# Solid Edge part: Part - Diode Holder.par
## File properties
Author: hhakima
Template: Normal.par
Last saved by: hhakima
Revision: 8
Application: Solid Edge
Density: 2712.000 kg/m^3
Accuracy: 0.990
Material: Aluminum, 6061-T6
Face Style: Aluminum
Fill Style: ANSI38(Aluminum)
Virtual Style: Polished aluminum
Coef. of Thermal Exp: 2.3e-05
Thermal Conductivity: 180.0
Specific Heat: 920.0
Modulus of Elasticity: 68947570000.0
Poission's Ratio: 0.33
Yield Stress: 275790280.0
Ultimate Stress: 310264065.0
Elongation: 0.0
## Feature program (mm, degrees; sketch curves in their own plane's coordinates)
sketch for "unnamed Protrusion 1" plane through (0, 0, 0) normal (0, 0, 1) x-axis (1, 0, 0)
  circle centre (0, 0) radius 5
extrude "unnamed Protrusion 1" add finite 5.5 along -normal
sketch for "ExtrudedCutout_1" plane through (0, 0, 0) normal (0, 0, 1) x-axis (0, 1, 0)
  circle centre (0, 0) radius 4
extrude "ExtrudedCutout_1" cut finite 2 along -normal
sketch for "ExtrudedCutout_2" plane through (0, 0, -2) normal (0, 0, 1) x-axis (0, 1, 0)
  circle centre (0, 0) radius 2.79
extrude "ExtrudedCutout_2" cut finite 1.2 along -normal
sketch for "unnamed Cutout 1" plane through (0, 0, -3.2) normal (0, 0, 1) x-axis (1, 0, 0)
  circle centre (0, 0) radius 2.25
extrude "unnamed Cutout 1" cut to key point along -normal
sketch for "ExtrudedCutout_4" #1 plane through (0, 0, -5.5) normal (0, 0, -1) x-axis (0, -1, 0)
  circle centre (0, 0) radius 4.35
sketch for "ExtrudedCutout_4" #2 plane through (0, 0, -5.5) normal (0, 0, -1) x-axis (0, -1, 0)
  circle centre (0, 0) radius 5
extrude "ExtrudedCutout_4" cut finite 3 along -normal
sketch for "ExtrudedCutout_5" plane through (0, 0, -5.5) normal (0, 0, -1) x-axis (-1, 0, 0)
  line (-8, -0.5) -> (8, -0.5)
  line (8, -0.5) -> (8, 0.5)
  line (8, 0.5) -> (-8, 0.5)
  line (-8, 0.5) -> (-8, -0.5)
extrude "ExtrudedCutout_5" cut finite 1 along -normal
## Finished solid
Body 1: solid body, 17 faces, 32 edges, 16 vertices.
  Faces by surface: plane 12, cylinder 5
  Edges by curve: circle 16, line 16
Bounding box of the edges (mm): 10.000 x 10.000 x 5.500, from (-5, -5, -5.5) to (5, 5, 0).
Cylindrical faces by radius (mm): R2.25 x1, R2.79 x1, R4 x1, R4.35 x1, R5 x1
Planar faces by outward normal: +y 2, +z 3, -y 2, -z 5
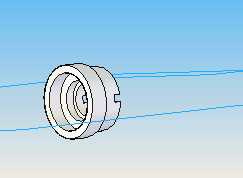
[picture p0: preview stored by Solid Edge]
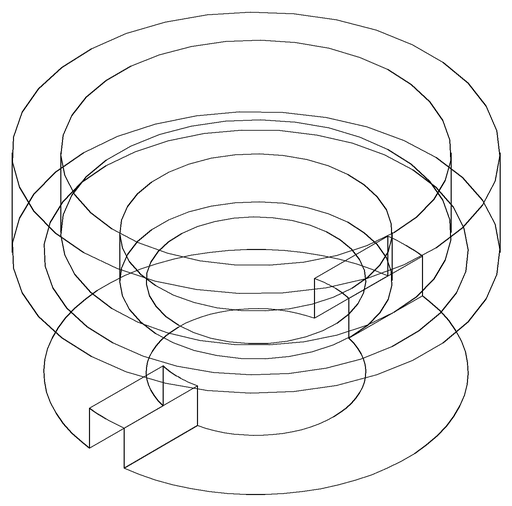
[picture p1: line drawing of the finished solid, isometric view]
